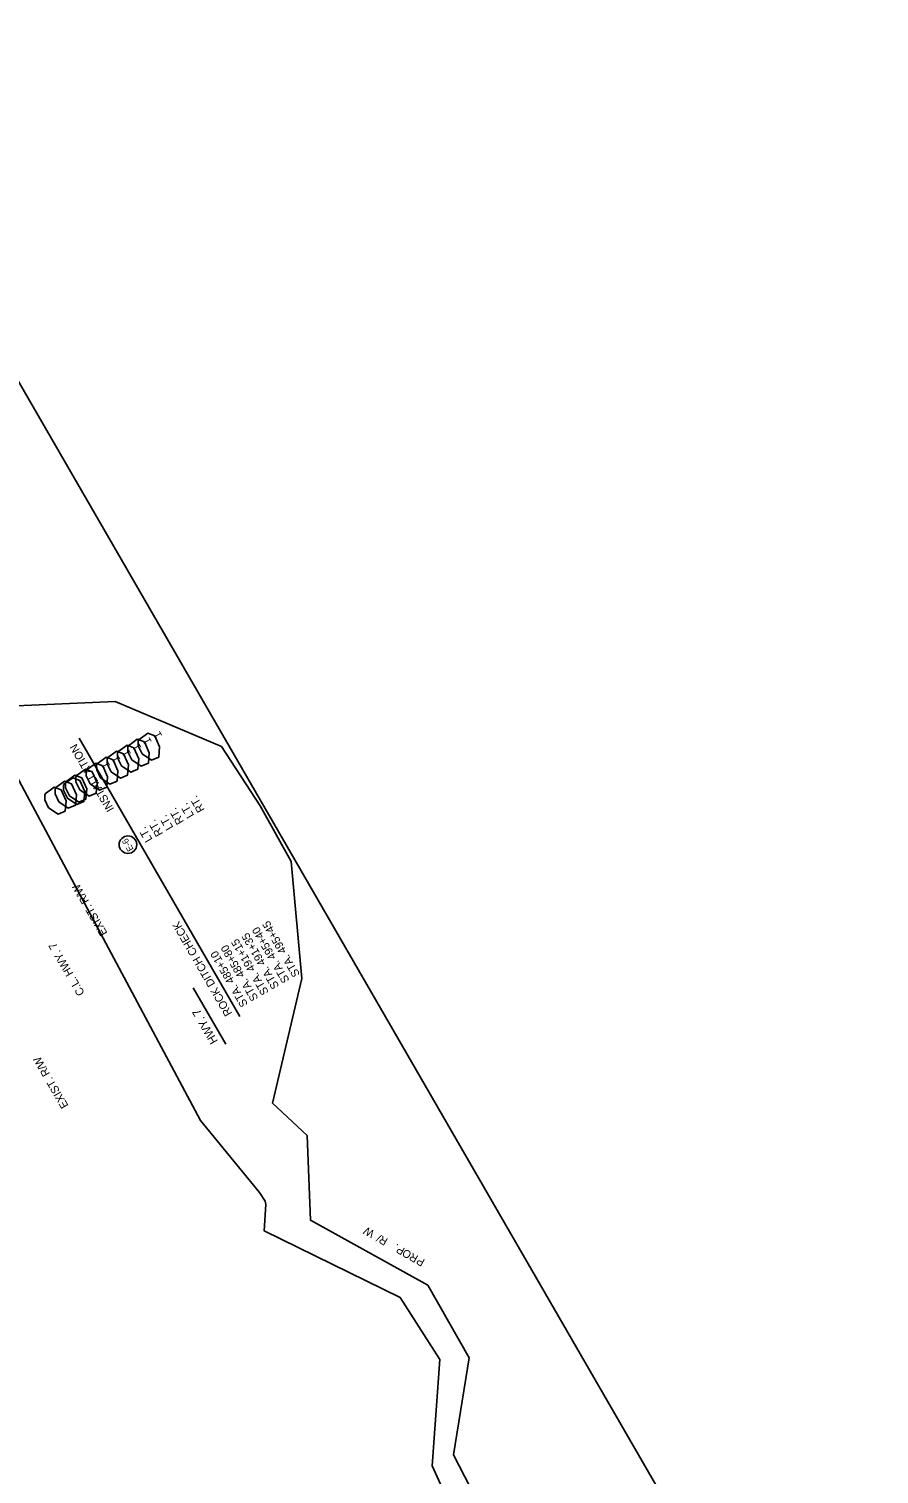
# Model space of a CAD drawing. Extents: x 956270 to 957915, y 1920520 to 1922423.
# Drawn here: x 957278 to 957915, y 1921340 to 1922423 of the extents above; entities that cross this region are included whole.
import ezdxf

# ---------------------------------------------------------------- set-up
doc = ezdxf.new("R2010")
doc.units = 0
for name, color, linetype in [('1', 7, 'Continuous'), ('44', 7, 'Continuous'), ('NO PLOT', 7, 'Continuous'), ('R_Draft', 7, 'Continuous'), ('S_TREE', 7, 'Continuous')]:
    doc.layers.add(name, color=color, linetype=linetype)

msp = doc.modelspace()

# ---------------------------------------------------------------- linework, layer by layer
at = {"layer": '1'}
msp.add_circle((957352.3, 1921811.6), 6.61, dxfattribs=at)
at = {"layer": '44'}
for p, q in [((957436.2, 1921682.8), (957315.7, 1921891.5)), ((957425.6, 1921662), (957401.2, 1921704.3))]:
    msp.add_line(p, q, dxfattribs=at)
at = {"layer": 'NO PLOT'}
msp.add_lwpolyline([(957915.2, 1921041.6), (957117.5, 1922423.2), (956666.2, 1922162.6), (956816.7, 1921902), (956875.1, 1921935.7), (957087.6, 1921567.7), (957029.2, 1921533.9), (957172.3, 1921286.1), (957225.7, 1921317), (957397.1, 1921020.2), (957343.6, 1920989.3), (957463.8, 1920781)], close=True, dxfattribs=at)
msp.add_lwpolyline([(957915.2, 1921041.6), (957117.5, 1922423.2), (956666.2, 1922162.6), (956816.7, 1921902), (956875.1, 1921935.7), (957087.6, 1921567.7), (957029.2, 1921533.9), (957172.3, 1921286.1), (957225.7, 1921317), (957397.1, 1921020.2), (957343.6, 1920989.3), (957463.8, 1920781)], close=True, dxfattribs=at)
msp.add_lwpolyline([(957915.2, 1921041.6), (957117.5, 1922423.2), (956666.2, 1922162.6), (956816.7, 1921902), (956875.1, 1921935.7), (957087.6, 1921567.7), (957029.2, 1921533.9), (957172.3, 1921286.1), (957225.7, 1921317), (957397.1, 1921020.2), (957343.6, 1920989.3), (957463.8, 1920781)], close=True, dxfattribs=at)
for points in [[(957704.5, 1921144.2), (957596.2, 1921354.1), (957607.9, 1921426.9), (957577.1, 1921481.2), (957489.2, 1921530), (957486.5, 1921593.6), (957460.7, 1921617.7), (957482.7, 1921711.3), (957474.6, 1921798.9), (957451.4, 1921840.8), (957422.3, 1921885.2), (957342.6, 1921919), (957257.4, 1921915.2)], [(957259.1, 1921881.5), (957406.6, 1921604.7), (957451, 1921550.9), (957455.1, 1921544.3), (957455.6, 1921541.9), (957454.3, 1921522.1), (957556.2, 1921472.1), (957586, 1921425.6), (957580.2, 1921345.8), (957625.4, 1921246.1)]]:
    msp.add_lwpolyline(points, dxfattribs=at)
at = {"layer": 'S_TREE'}
for points in [[(957352.6, 1921885.8), (957359.3, 1921890.6), (957364.6, 1921888.7), (957368.2, 1921880.4), (957367.6, 1921872.8), (957362.2, 1921870.5), (957355.2, 1921875.3), (957352.2, 1921881.3), (957352.2, 1921885), (957353.2, 1921886.4)], [(957352.6, 1921885.8), (957359.3, 1921890.6), (957364.6, 1921888.7), (957368.2, 1921880.4), (957367.6, 1921872.8), (957362.2, 1921870.5), (957355.2, 1921875.3), (957352.2, 1921881.3), (957352.2, 1921885), (957353.2, 1921886.4)], [(957360.4, 1921890.3), (957367.1, 1921895.1), (957372.4, 1921893.2), (957376, 1921884.9), (957375.4, 1921877.3), (957370, 1921875), (957363, 1921879.8), (957360, 1921885.8), (957360, 1921889.5), (957361, 1921890.9)], [(957329.2, 1921872.3), (957336, 1921877.1), (957341.2, 1921875.2), (957344.8, 1921866.9), (957344.2, 1921859.3), (957338.8, 1921857), (957331.8, 1921861.8), (957328.9, 1921867.8), (957328.8, 1921871.5), (957329.8, 1921872.9)], [(957337, 1921876.8), (957343.8, 1921881.6), (957349, 1921879.7), (957352.6, 1921871.4), (957352, 1921863.8), (957346.6, 1921861.5), (957339.6, 1921866.3), (957336.7, 1921872.3), (957336.6, 1921876), (957337.6, 1921877.4)], [(957344.8, 1921881.3), (957351.6, 1921886.1), (957356.8, 1921884.2), (957360.4, 1921875.9), (957359.8, 1921868.3), (957354.4, 1921866), (957347.4, 1921870.8), (957344.5, 1921876.8), (957344.4, 1921880.5), (957345.4, 1921881.9)], [(957344.8, 1921881.3), (957351.6, 1921886.1), (957356.8, 1921884.2), (957360.4, 1921875.9), (957359.8, 1921868.3), (957354.4, 1921866), (957347.4, 1921870.8), (957344.5, 1921876.8), (957344.4, 1921880.5), (957345.4, 1921881.9)], [(957313.6, 1921863.3), (957320.4, 1921868.1), (957325.6, 1921866.2), (957329.3, 1921857.9), (957328.6, 1921850.3), (957323.2, 1921848), (957316.2, 1921852.8), (957313.3, 1921858.8), (957313.2, 1921862.5), (957314.2, 1921863.9)], [(957313.6, 1921863.3), (957320.4, 1921868.1), (957325.6, 1921866.2), (957329.3, 1921857.9), (957328.6, 1921850.3), (957323.2, 1921848), (957316.2, 1921852.8), (957313.3, 1921858.8), (957313.2, 1921862.5), (957314.2, 1921863.9)], [(957313.6, 1921863.3), (957320.4, 1921868.1), (957325.6, 1921866.2), (957329.3, 1921857.9), (957328.6, 1921850.3), (957323.2, 1921848), (957316.2, 1921852.8), (957313.3, 1921858.8), (957313.2, 1921862.5), (957314.2, 1921863.9)], [(957313.6, 1921863.3), (957320.4, 1921868.1), (957325.6, 1921866.2), (957329.3, 1921857.9), (957328.6, 1921850.3), (957323.2, 1921848), (957316.2, 1921852.8), (957313.3, 1921858.8), (957313.2, 1921862.5), (957314.2, 1921863.9)], [(957321.4, 1921867.8), (957328.2, 1921872.6), (957333.4, 1921870.7), (957337, 1921862.4), (957336.4, 1921854.8), (957331, 1921852.5), (957324, 1921857.3), (957321.1, 1921863.3), (957321, 1921867), (957322, 1921868.4)], [(957321.4, 1921867.8), (957328.2, 1921872.6), (957333.4, 1921870.7), (957337, 1921862.4), (957336.4, 1921854.8), (957331, 1921852.5), (957324, 1921857.3), (957321.1, 1921863.3), (957321, 1921867), (957322, 1921868.4)], [(957321.4, 1921867.8), (957328.2, 1921872.6), (957333.4, 1921870.7), (957337, 1921862.4), (957336.4, 1921854.8), (957331, 1921852.5), (957324, 1921857.3), (957321.1, 1921863.3), (957321, 1921867), (957322, 1921868.4)], [(957321.4, 1921867.8), (957328.2, 1921872.6), (957333.4, 1921870.7), (957337, 1921862.4), (957336.4, 1921854.8), (957331, 1921852.5), (957324, 1921857.3), (957321.1, 1921863.3), (957321, 1921867), (957322, 1921868.4)], [(957321.4, 1921867.8), (957328.2, 1921872.6), (957333.4, 1921870.7), (957337, 1921862.4), (957336.4, 1921854.8), (957331, 1921852.5), (957324, 1921857.3), (957321.1, 1921863.3), (957321, 1921867), (957322, 1921868.4)], [(957298, 1921854.3), (957304.8, 1921859.1), (957310, 1921857.2), (957313.7, 1921848.9), (957313, 1921841.3), (957307.6, 1921839), (957300.6, 1921843.8), (957297.7, 1921849.8), (957297.7, 1921853.5), (957298.6, 1921854.9)], [(957298, 1921854.3), (957304.8, 1921859.1), (957310, 1921857.2), (957313.7, 1921848.9), (957313, 1921841.3), (957307.6, 1921839), (957300.6, 1921843.8), (957297.7, 1921849.8), (957297.7, 1921853.5), (957298.6, 1921854.9)], [(957298, 1921854.3), (957304.8, 1921859.1), (957310, 1921857.2), (957313.7, 1921848.9), (957313, 1921841.3), (957307.6, 1921839), (957300.6, 1921843.8), (957297.7, 1921849.8), (957297.7, 1921853.5), (957298.6, 1921854.9)], [(957304.3, 1921857), (957311.1, 1921861.7), (957316.3, 1921859.8), (957320, 1921851.5), (957319.3, 1921843.9), (957313.9, 1921841.7), (957306.9, 1921846.4), (957304, 1921852.4), (957303.9, 1921856.1), (957304.9, 1921857.5)], [(957305.8, 1921858.8), (957312.6, 1921863.6), (957317.8, 1921861.7), (957321.5, 1921853.4), (957320.8, 1921845.8), (957315.4, 1921843.5), (957308.4, 1921848.3), (957305.5, 1921854.3), (957305.5, 1921858), (957306.4, 1921859.4)], [(957305.8, 1921858.8), (957312.6, 1921863.6), (957317.8, 1921861.7), (957321.5, 1921853.4), (957320.8, 1921845.8), (957315.4, 1921843.5), (957308.4, 1921848.3), (957305.5, 1921854.3), (957305.5, 1921858), (957306.4, 1921859.4)], [(957305.8, 1921858.8), (957312.6, 1921863.6), (957317.8, 1921861.7), (957321.5, 1921853.4), (957320.8, 1921845.8), (957315.4, 1921843.5), (957308.4, 1921848.3), (957305.5, 1921854.3), (957305.5, 1921858), (957306.4, 1921859.4)], [(957305.8, 1921858.8), (957312.6, 1921863.6), (957317.8, 1921861.7), (957321.5, 1921853.4), (957320.8, 1921845.8), (957315.4, 1921843.5), (957308.4, 1921848.3), (957305.5, 1921854.3), (957305.5, 1921858), (957306.4, 1921859.4)], [(957305.8, 1921858.8), (957312.6, 1921863.6), (957317.8, 1921861.7), (957321.5, 1921853.4), (957320.8, 1921845.8), (957315.4, 1921843.5), (957308.4, 1921848.3), (957305.5, 1921854.3), (957305.5, 1921858), (957306.4, 1921859.4)], [(957290.2, 1921849.8), (957297, 1921854.6), (957302.2, 1921852.7), (957305.9, 1921844.4), (957305.2, 1921836.8), (957299.9, 1921834.5), (957292.8, 1921839.3), (957289.9, 1921845.3), (957289.9, 1921849), (957290.8, 1921850.4)]]:
    msp.add_lwpolyline(points, dxfattribs=at)

# ---------------------------------------------------------------- texts
at = {"layer": '1'}
msp.add_text('E-6 ', height=4.8, rotation=120, dxfattribs=at).set_placement((957356.7, 1921808.2))
at = {"layer": '44'}
for s, height, p in [('1', 6, (957370.4, 1921888.7)), ('1', 6, (957378.2, 1921893.2)), ('INSTALLATION', 6, (957342.1, 1921838.3)), ('1', 6, (957347, 1921875.2)), ('1', 6, (957354.8, 1921879.7)), ('1', 6, (957362.6, 1921884.2)), ('1', 6, (957339.2, 1921870.7)), ('RT.', 6, (957410, 1921837.8)), ('LT.', 6, (957386.5, 1921824.5)), ('RT.', 6, (957394.4, 1921828.8)), ('LT.', 6, (957402.1, 1921833.5)), ('LT.', 6, (957370.9, 1921815.5)), ('RT.', 6, (957378.8, 1921819.8)), ('ROCK DITCH CHECK', 6, (957430.6, 1921685.1)), ('STA. 495+40', 6, (957473.6, 1921709.9)), ('STA. 495+45', 6, (957481.4, 1921714.4)), ('STA. 491+15', 6, (957458, 1921700.9)), ('STA. 491+35', 6, (957465.8, 1921705.4)), ('STA. 485+10', 6, (957442.4, 1921691.9)), ('STA. 485+80', 6, (957450.2, 1921696.4)), ('HWY. 7', 6.25, (957419.9, 1921664.3))]:
    msp.add_text(s, height=height, rotation=120, dxfattribs=at).set_placement(p)
at = {"layer": 'R_Draft'}
for s, rotation, p in [('EXIST. R/W', 119.9486, (957337.1, 1921745.3)), ('C.L. HWY. 7', 120.2975, (957320.1, 1921700.4)), ('EXIST. R/W', 119.9486, (957307.9, 1921615.9)), ('W', 150.5183, (957537.6, 1921521.6)), ('/', 150.5183, (957542.7, 1921518.7)), ('R', 150.5183, (957547.6, 1921515.9)), ('P', 150.5183, (957560.3, 1921508.7)), ('.', 150.5183, (957555.4, 1921511.5)), ('O', 150.5183, (957565.4, 1921505.8)), ('R', 150.5183, (957570.3, 1921503)), ('P', 150.5183, (957575.3, 1921500.2))]:
    msp.add_text(s, height=6, rotation=rotation, dxfattribs=at).set_placement(p)

doc.saveas('drawing.dxf')
